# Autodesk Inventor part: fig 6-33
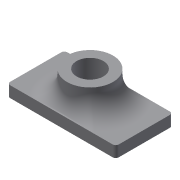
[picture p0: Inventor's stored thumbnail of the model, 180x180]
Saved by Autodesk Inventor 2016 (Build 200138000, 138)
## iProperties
Created: 2004-05
Part Number: fig 6-33
Document SubType Name: Modeling
Designer: CADCIM Technologies
Manufacturer: Standard
Standards Organization: Custom
Density: 1 g/cm^3
Material: Generic
Appearance: Default
Author: CADCIM Technologies
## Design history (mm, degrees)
sketch "Sketch1"
  geometry: L1 (-39.276, -18.692)-(33.721, -18.692); L2 (33.721, -18.692)-(33.721, 19.728); L3 (33.721, 19.728)-(-39.276, 19.728); L4 (-39.276, 19.728)-(-39.276, -18.692)
  constraints: 8 end point, 2 parallel, 1 horizontal, 1 perpendicular
extrude "Extrusion1" new body sketch "Sketch1" distance "d0" = 7.5; taper "d1" = 0 deg
fillet "Fillet1" dims "d2" = 2
sketch "Sketch2"
  geometry: C1 r 15.456 at (-2.778, 0.518)
  constraints: 1 centre point
extrude "Extrusion2" join sketch "Sketch2" distance "d3" = 17.25; taper "d4" = 0 deg
hole "Hole1" diameter "d8" = 18; stored, may be unused: countersink angle "d12" = 90 deg, drill point angle "d14" = 118 deg; dims "d6" = 10, "d7" = 10, "d9" = 6, "d10" = 4, "d11" = 2, "d13" = 8
fillet "Fillet2" dims "d5" = 14
body "Solid1"
